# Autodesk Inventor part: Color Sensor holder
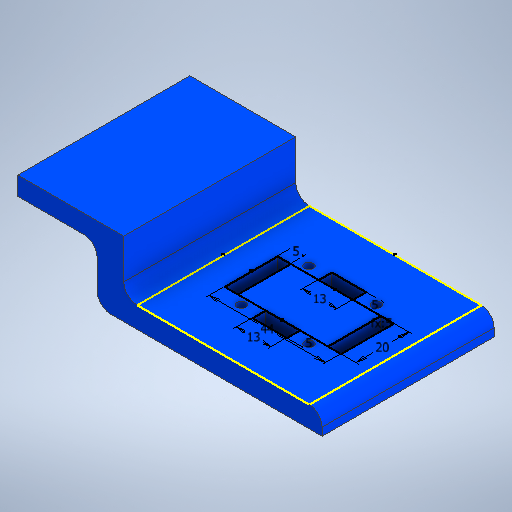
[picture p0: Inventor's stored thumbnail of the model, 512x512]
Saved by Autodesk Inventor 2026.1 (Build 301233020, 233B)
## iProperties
Created: 2026-11
Part Number: Color Sensor holder
Material: Generic
Document SubType Name: Modeling
Designer: hp
Density: 1 g/cm^3
Appearance: Default
Author: hp
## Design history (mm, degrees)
sketch "Sketch1"
  geometry: L1 (0, 0)-(0, 28); L2 (0, 28)-(10, 28); L3 (10, 28)-(10, 8); L4 (10, 8)-(85, 8); L5 (85, 8)-(85, 0); L6 (85, 0)-(0, 0); L7 (47.5, 8)-(47.5, 0); L8 (10, 0)-(95, 0); L9 (0, 21)-(-30, 21); L10 (-30, 21)-(-30, 28); L11 (-30, 28)-(0, 28); 1 further point
  constraints: 22 end point, 8 perpendicular, 2 point on line, 2 symmetric about line, 1 horizontal, 1 midpoint, 1 vertical
  dimensions: "d0" = 28 distance of L1.start L1.end; "d1" = 10 distance of L1.end L2.end; "d2" = 20 distance of L2.end L3.end; "d3" = 75 distance of L3.end L4.end; "d18" = 30 distance of L9.start L9.end; "d19" = 7 distance of L9.end L10.end
extrude "Extrusion1" new body sketch "Sketch1" distance "d4" = 65; taper "d5" = 0 deg
fillet "Fillet1" dims "d6" = 5
fillet "Fillet2" dims "d7" = 5
sketch "Sketch2"
  geometry: L1 (65, 65)-(65, 0) reference; L2 (65, 65)-(0, 65) reference; L3 (0, 0)-(0, 65) reference; L4 (65, 0)-(0, 0) reference; L5 (10.5, 42.5)-(54.5, 42.5); L6 (54.5, 42.5)-(54.5, 22.5); L7 (54.5, 22.5)-(10.5, 22.5); L8 (10.5, 22.5)-(10.5, 42.5); L9 (26, 22.5)-(39, 22.5); L10 (39, 22.5)-(39, 17.5); L11 (39, 17.5)-(26, 17.5); L12 (26, 17.5)-(26, 22.5); L13 (26, 47.5)-(39, 47.5); L14 (39, 47.5)-(39, 42.5); L15 (26, 42.5)-(26, 47.5); L16 (39, 42.5)-(26, 42.5); L17 (15.5, 22.5)-(15.5, 42.5); L18 (49.5, 22.5)-(49.5, 42.5); 10 further points
  constraints: 28 end point, 7 midpoint, 6 parallel, 5 perpendicular, 4 point on line, 3 horizontal, 1 horizontal alignment, 1 vertical alignment
  dimensions: "d8" = 44 distance of L6.end L7.end; "d9" = 20 distance of L5.end L6.end; "d10" = 13 distance of L10.end L11.end; "d11" = 5 distance of L9.end L10.end; "d12" = 13 distance of L14.end L15.start; "d13" = 5 distance of L13.end L14.end; "d16" = 5 distance between parallel lines of L17 L8; "d17" = 5 distance between parallel lines of L6 L18 (= d16)
extrude "Extrusion2" cut sketch "Sketch2" extent not by distance; stored distance "d14" = 60; taper "d15" = 0 deg
fillet "Fillet3" dims "d20" = 5
sketch "Sketch4"
  geometry: L1 (25, 65)-(25, 0) reference; L2 (0, 65)-(25, 65) reference; L3 (0, 0)-(0, 65) reference; L4 (0, 0)-(25, 0) reference; C1 r 2.5 at (12.5, 49); C2 r 2.5 at (12.5, 16); 5 further points
  constraints: 2 centre point, 2 coincident, 2 midpoint, 2 vertical alignment
  dimensions: "d28" = 5 diameter of C1; "d29" = 5 diameter of C2 (= d28); "d30" = 16 distance from line of L2 C1.centre; "d31" = 16 distance from line of L4 C2.centre (= d30)
  node "Projected Loop2"
sketch "Sketch6"
  geometry: 4 further points
hole "Hole3" sketch "Sketch6" at (-50.25, 45.25), (-24.75, 45.25), (-24.75, 19.75), (-50.25, 19.75) diameter "d39" = 3.4; stored, may be unused: countersink angle "d43" = 90 deg, drill point angle "d45" = 0 deg; dims "d40" = 6, "d41" = 4, "d42" = 2, "d44" = 8
body "Solid1"
node "Projected Loop1"
